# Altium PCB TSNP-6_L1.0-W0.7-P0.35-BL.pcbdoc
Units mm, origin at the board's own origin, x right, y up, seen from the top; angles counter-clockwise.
Board outline 14.03 x 13.96 mm, 2 copper layers (Top Layer, Bottom Layer), stack 0 mm thick; 1 components, 0 nets, 6 pads, 0 vias.
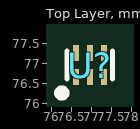
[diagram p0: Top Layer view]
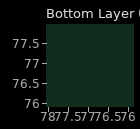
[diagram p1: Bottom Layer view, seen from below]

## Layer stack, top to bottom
Top Layer: signal copper (thickness not stored)
Bottom Layer: signal copper (thickness not stored)

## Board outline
83.883,69.85 69.85,69.85 69.85,83.813 83.883,83.813

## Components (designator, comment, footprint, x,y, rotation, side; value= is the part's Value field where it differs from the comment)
U? "" TSNP-6_L1.0-W0.7-P0.35-BL 76.963,76.963 r0 top

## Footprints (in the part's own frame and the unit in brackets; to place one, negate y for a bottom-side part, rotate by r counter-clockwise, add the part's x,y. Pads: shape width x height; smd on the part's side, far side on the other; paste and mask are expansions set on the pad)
TSNP-6_L1.0-W0.7-P0.35-BL [mm]
  rect 0.15x0.4 smd: 1(-0.35,-0.3) 2(0,-0.3) 3(0.35,-0.3) 4(0.35,0.3) 5(0,0.3) 6(-0.35,0.3)
  silkscreen extent -0.76,-0.76 0.57,0.35

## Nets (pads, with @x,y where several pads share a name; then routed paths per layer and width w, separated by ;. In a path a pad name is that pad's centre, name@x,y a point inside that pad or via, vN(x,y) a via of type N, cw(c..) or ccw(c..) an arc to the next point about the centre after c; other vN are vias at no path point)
pads on no net: U?.1 U?.2 U?.3 U?.4 U?.5 U?.6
